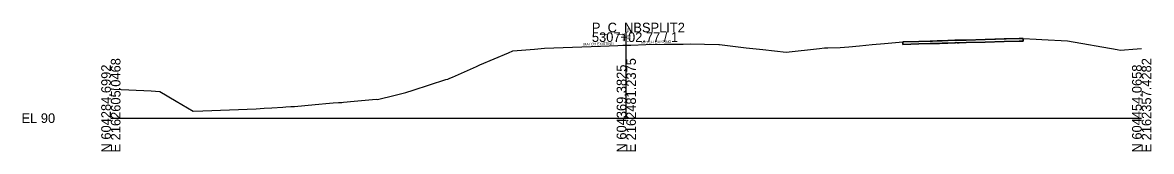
# Model space of a CAD drawing. Extents: x -26 to 1303, y -10 to 12038.
# Drawn here: x 974.3 to 1302.8, y 1990.3 to 2027.8 of the extents above; entities that cross this region are included whole.
import ezdxf

# ---------------------------------------------------------------- set-up
doc = ezdxf.new("R2010")
doc.units = 0
for name, color, linetype in [('RD_GPK_XS_Cell', 7, 'Continuous'), ('RD_XS_ExGround', 7, 'Continuous'), ('RD_XS_ExPaveRet', 7, 'Continuous'), ('RD_XS_TX_Elev_EX', 7, 'Continuous'), ('RD_XS_TX_Elev_PR', 7, 'Continuous'), ('RD_XS_TX_Slope', 7, 'Continuous')]:
    doc.layers.add(name, color=color, linetype=linetype)

msp = doc.modelspace()

# ---------------------------------------------------------------- linework, layer by layer
at = {"layer": 'RD_GPK_XS_Cell'}
for p, q in [((1150, 2000), (1150, 2025)), ((1000, 2000), (1150, 2000)), ((1150, 2000), (1300, 2000))]:
    msp.add_line(p, q, dxfattribs=at)
at = {"layer": 'RD_XS_ExGround'}
msp.add_lwpolyline([(1000, 2008.49), (1000.14, 2008.5), (1000.89, 2008.49), (1011.71, 2007.94), (1014.24, 2007.79), (1019.03, 2004.96), (1023.91, 2002.06), (1026.81, 2002.15), (1042.32, 2002.69), (1044.61, 2002.87), (1046.87, 2003.05), (1050.01, 2003.23), (1050.97, 2003.28), (1052.41, 2003.39), (1052.77, 2003.4), (1053.42, 2003.41), (1059.45, 2004), (1063.62, 2004.38), (1064.72, 2004.48), (1066.21, 2004.55), (1067.22, 2004.58), (1067.74, 2004.63), (1070.82, 2004.95), (1077.26, 2005.5), (1077.57, 2005.48), (1082.77, 2006.72), (1085.45, 2007.36), (1085.84, 2007.46), (1088.01, 2008.17), (1097.48, 2011.28), (1098.05, 2011.4), (1098.63, 2011.6), (1099.39, 2011.96), (1106.43, 2015.04), (1107.42, 2015.5), (1115.71, 2019.03), (1117.03, 2019.6), (1123.31, 2020.11), (1126.24, 2020.38), (1142.46, 2020.97), (1147.56, 2021.15), (1149.02, 2021.21), (1150.48, 2021.26), (1151.36, 2021.29), (1155.71, 2021.44), (1161.02, 2021.52), (1164.63, 2021.58), (1166.58, 2021.58), (1168.59, 2021.62), (1176.92, 2021.5), (1177.11, 2021.48), (1184.85, 2020.5), (1189.7, 2019.96), (1196.55, 2019.19), (1206.22, 2020.31), (1207.65, 2020.5), (1208.7, 2020.51), (1212.29, 2020.56), (1214.78, 2020.82), (1217.91, 2021.1), (1221.57, 2021.5), (1225.12, 2021.77), (1230.48, 2022.22), (1239.11, 2022.47), (1241.07, 2022.53), (1241.83, 2022.56), (1245.65, 2022.69), (1245.95, 2022.75), (1246.27, 2022.71), (1246.34, 2022.73), (1246.86, 2022.69), (1254.44, 2022.92), (1260.58, 2023.1), (1265.5, 2023.21), (1269.27, 2022.99), (1270.9, 2022.91), (1278.38, 2022.5), (1292.85, 2019.96), (1293.72, 2019.8), (1298.68, 2020.18), (1300, 2020.28)], dxfattribs=at)
at = {"layer": 'RD_XS_ExPaveRet'}
for points in [[(1265, 2023.2), (1265.5, 2023.21), (1265.5, 2022.73), (1265.5, 2022.46), (1265, 2022.45), (1264.38, 2022.43), (1259.96, 2022.33), (1254.45, 2022.17), (1248.94, 2022), (1246.86, 2021.94), (1246.48, 2021.97), (1246.34, 2021.98), (1246.32, 2021.97), (1246.27, 2021.96), (1246.05, 2021.99), (1245.95, 2022), (1245.79, 2021.97), (1245.65, 2021.94), (1243.57, 2021.87), (1241.95, 2021.81), (1241.15, 2021.79), (1241.08, 2021.79), (1240.49, 2021.77), (1238.42, 2021.7), (1235.14, 2021.6), (1230.48, 2021.47), (1230.48, 2021.75), (1230.48, 2022.22), (1235.14, 2022.35), (1238.42, 2022.45), (1240.49, 2022.52), (1241.08, 2022.54), (1241.15, 2022.54), (1241.95, 2022.56), (1243.57, 2022.62), (1245.65, 2022.69), (1245.79, 2022.72), (1245.95, 2022.75), (1246.05, 2022.74), (1246.27, 2022.71), (1246.32, 2022.72), (1246.34, 2022.73), (1246.48, 2022.72), (1246.86, 2022.69), (1248.94, 2022.75), (1254.45, 2022.92), (1259.96, 2023.08), (1264.38, 2023.18), (1265, 2023.2)], [(1264.38, 2023.18), (1259.96, 2023.08), (1254.45, 2022.92), (1248.94, 2022.75), (1246.86, 2022.69), (1246.48, 2022.72), (1246.34, 2022.73), (1246.32, 2022.72), (1246.27, 2022.71), (1246.05, 2022.74), (1245.95, 2022.75), (1245.79, 2022.72), (1245.65, 2022.69), (1243.57, 2022.62), (1241.95, 2022.56), (1241.15, 2022.54), (1241.08, 2022.54), (1240.49, 2022.52), (1238.42, 2022.45), (1235.14, 2022.35), (1230.48, 2022.22), (1230.48, 2021.75), (1230.48, 2021.47), (1235.14, 2021.6), (1238.42, 2021.7), (1240.49, 2021.77), (1241.08, 2021.79), (1241.15, 2021.79), (1241.95, 2021.81), (1243.57, 2021.87), (1245.65, 2021.94), (1245.79, 2021.97), (1245.95, 2022), (1246.05, 2021.99), (1246.27, 2021.96), (1246.32, 2021.97), (1246.34, 2021.98), (1246.48, 2021.97), (1246.86, 2021.94), (1248.94, 2022), (1254.45, 2022.17), (1259.96, 2022.33), (1264.38, 2022.43), (1265, 2022.45), (1265.5, 2022.46), (1265.5, 2022.73), (1265.5, 2023.21), (1265, 2023.2), (1264.38, 2023.18)]]:
    msp.add_lwpolyline(points, dxfattribs=at)

# ---------------------------------------------------------------- texts
at = {"layer": 'RD_GPK_XS_Cell'}
for s, p in [('P_C_NBSPLIT2', (1140, 2025)), ('5307+02.77 / 1', (1140, 2022.2)), ('EL 90', (974, 1998.6))]:
    msp.add_text(s, height=2.8, dxfattribs=at).set_placement(p)
for s, p in [('E 2162605.0468', (1002.8, 1990)), ('E 2162481.2375', (1152.8, 1990)), ('E 2162357.4282', (1302.8, 1990)), ('N 604284.6992', (1000, 1990)), ('N 604369.3825', (1150, 1990)), ('N 604454.0658', (1300, 1990))]:
    msp.add_text(s, height=2.8, rotation=90, dxfattribs=at).set_placement(p)
at = {"layer": 'RD_XS_TX_Elev_EX'}
msp.add_text('111.25', height=0.6, rotation=90, dxfattribs=at).set_placement((1149.59, 2022.28))
at = {"layer": 'RD_XS_TX_Elev_PR'}
msp.add_text('111.25', height=1, rotation=90, dxfattribs=at).set_placement((1151.17, 2022.03))
at = {"layer": 'RD_XS_TX_Slope'}
for p in [(1137.55, 2021.13), (1154.31, 2021.69)]:
    msp.add_text('MATCH EXISTING', height=0.75, rotation=1.6039, dxfattribs=at).set_placement(p)

doc.saveas('drawing.dxf')
